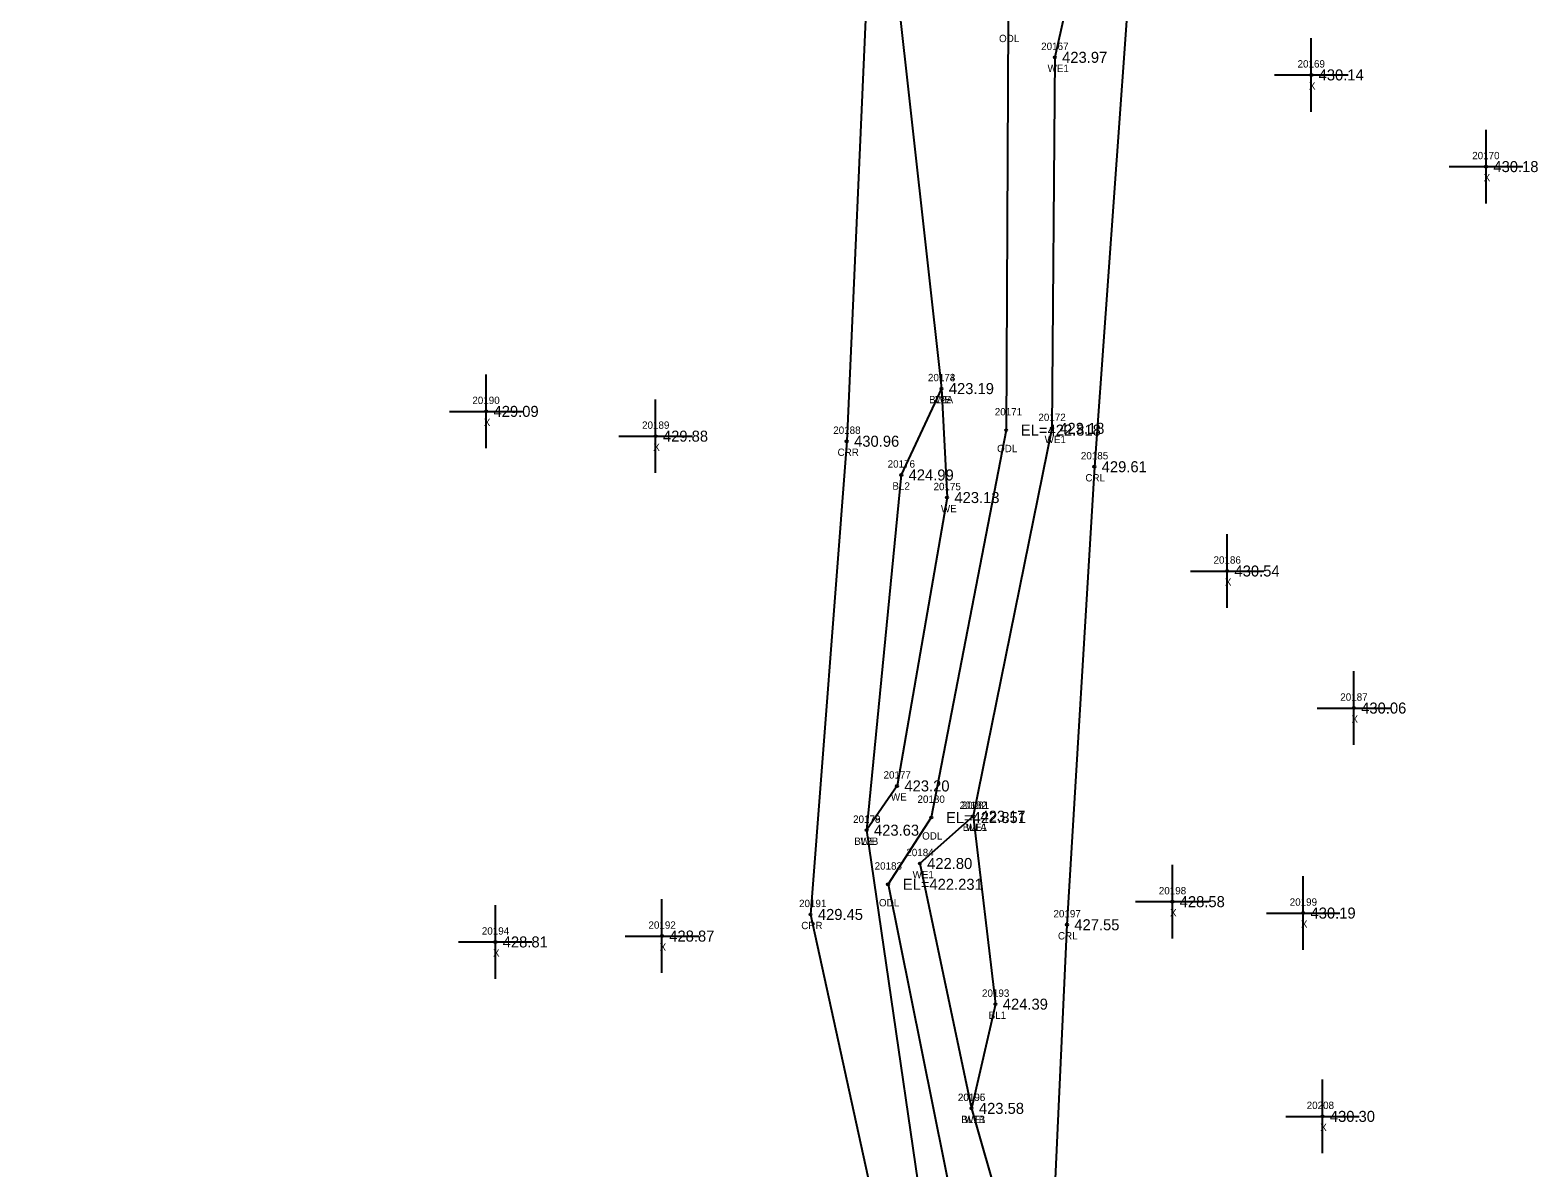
# Model space of a CAD drawing. Extents: x 1858461 to 1858936, y 1147060 to 1148183.
# Drawn here: x 1858722.2 to 1858927.2, y 1147876.4 to 1148031.1 of the extents above; entities that cross this region are included whole.
import ezdxf

# ---------------------------------------------------------------- set-up
doc = ezdxf.new("R2010")
doc.units = 0
for name, color, linetype in [('RD_DTM_BkLn1', 7, 'Continuous'), ('RD_DTM_BkLn_txCode', 7, 'Continuous'), ('RD_EX_H2O', 7, 'Continuous'), ('RD_EX_H2O_txCode', 7, 'Continuous'), ('RD_EX_Misc', 7, 'Continuous'), ('RD_EX_Misc_txCode', 7, 'Continuous'), ('RD_EX_TX_H2O_ELEV', 7, 'Continuous'), ('RD_EX_TX_Misc_ELEV', 7, 'Continuous'), ('RD_SMD_Locator', 7, 'Continuous')]:
    doc.layers.add(name, color=color, linetype=linetype)

msp = doc.modelspace()

# ---------------------------------------------------------------- linework, layer by layer
at = {"layer": 'RD_DTM_BkLn1'}
for points in [[(1858846.14, 1147982.36), (1858840.67, 1147970.61), (1858835.96, 1147922.3)], [(1858850.44, 1147924.2), (1858853.48, 1147898.64), (1858850.23, 1147884.47)]]:
    msp.add_lwpolyline(points, dxfattribs=at)
at = {"layer": 'RD_EX_H2O'}
for points in [[(1858883.69, 1148147.48), (1858852.78, 1148112.64), (1858836.04, 1148037.73), (1858833.26, 1147975.2), (1858828.33, 1147910.84), (1858842, 1147848.22), (1858847.52, 1147794.04), (1858841.16, 1147786.48), (1858816.23, 1147769.28), (1858759.58, 1147742.8), (1858751.47, 1147732.35), (1858731.2, 1147689.66), (1858724.77, 1147677.64), (1858718.76, 1147662.14), (1858713.87, 1147646.5), (1858696.23, 1147629.99), (1858681.73, 1147631.9), (1858663.61, 1147613.98)], [(1858909.91, 1148115.72), (1858902.77, 1148116.75), (1858903.07, 1148125.04), (1858896.61, 1148132.76), (1858873.78, 1148129.33), (1858855.27, 1148111.83), (1858840.09, 1148036.93), (1858846.14, 1147982.36), (1858846.9, 1147967.54), (1858840.1, 1147928.32), (1858835.96, 1147922.3), (1858846.22, 1147851.69), (1858849.56, 1147834.44), (1858863.29, 1147789.22), (1858867.71, 1147772.35), (1858865.71, 1147761.59), (1858842.61, 1147761.06), (1858828.27, 1147754.21), (1858821.34, 1147763.04), (1858764.94, 1147737.1), (1858734.3, 1147688.97), (1858719.03, 1147640.86), (1858697.04, 1147613.49)], [(1858867.04, 1148108.26), (1858855.22, 1148032.48), (1858854.94, 1147976.71), (1858844.75, 1147924.02), (1858838.88, 1147914.94), (1858851.14, 1147854.11), (1858872.36, 1147792.48), (1858884.3, 1147779.68), (1858885.3, 1147773.97), (1858872.32, 1147746.91), (1858824.97, 1147749.39), (1858805.62, 1147746.07), (1858768.36, 1147727.81), (1858744.99, 1147687.5), (1858739.82, 1147673.18), (1858724.58, 1147638.24), (1858698.73, 1147607.87)], [(1858878.92, 1148104.66), (1858861.55, 1148027.41), (1858861.16, 1147976.95), (1858850.44, 1147924.2), (1858843.19, 1147917.77), (1858850.23, 1147884.47), (1858857.83, 1147857.85), (1858871.27, 1147824.7), (1858889.75, 1147780), (1858881.97, 1147738.22), (1858867.37, 1147736.75), (1858826.32, 1147742.88), (1858795.91, 1147734.53), (1858775.64, 1147718.51), (1858753.77, 1147690.47), (1858731.96, 1147634.67), (1858700.72, 1147599.99)], [(1858879.83, 1148102.54), (1858871.42, 1148034.27), (1858866.93, 1147971.73), (1858863.21, 1147909.44), (1858860.9, 1147860.04), (1858873.82, 1147825.54), (1858891.79, 1147781.55), (1858894.95, 1147773.07), (1858887.01, 1147735.25), (1858825.08, 1147733.03), (1858791.14, 1147702.41), (1858765.02, 1147654.77), (1858740.99, 1147628.76), (1858706.35, 1147596.83), (1858671.87, 1147580.02), (1858637.61, 1147560.56), (1858613.46, 1147539.88), (1858609.2, 1147499), (1858608.26, 1147474.71), (1858583.43, 1147442.99), (1858542.68, 1147417.32), (1858497.34, 1147430.55)]]:
    msp.add_lwpolyline(points, dxfattribs=at)
at = {"layer": 'RD_EX_Misc'}
for p, q in [((1858896.43, 1148020.02), (1858896.43, 1148030.02)), ((1858891.43, 1148025.02), (1858901.43, 1148025.02)), ((1858920.2, 1148007.55), (1858920.2, 1148017.55)), ((1858915.2, 1148012.55), (1858925.2, 1148012.55)), ((1858784.22, 1147974.26), (1858784.22, 1147984.26)), ((1858779.22, 1147979.26), (1858789.22, 1147979.26)), ((1858807.26, 1147970.89), (1858807.26, 1147980.89)), ((1858802.26, 1147975.89), (1858812.26, 1147975.89)), ((1858884.99, 1147952.55), (1858884.99, 1147962.55)), ((1858879.99, 1147957.55), (1858889.99, 1147957.55)), ((1858902.22, 1147933.91), (1858902.22, 1147943.91)), ((1858897.22, 1147938.91), (1858907.22, 1147938.91)), ((1858877.54, 1147907.58), (1858877.54, 1147917.58)), ((1858895.33, 1147906.03), (1858895.33, 1147916.03)), ((1858785.47, 1147902.1), (1858785.47, 1147912.1)), ((1858808.12, 1147902.9), (1858808.12, 1147912.9)), ((1858872.54, 1147912.58), (1858882.54, 1147912.58)), ((1858890.33, 1147911.03), (1858900.33, 1147911.03)), ((1858803.12, 1147907.9), (1858813.12, 1147907.9)), ((1858780.47, 1147907.1), (1858790.47, 1147907.1)), ((1858897.96, 1147878.38), (1858897.96, 1147888.38)), ((1858892.96, 1147883.38), (1858902.96, 1147883.38))]:
    msp.add_line(p, q, dxfattribs=at)
at = {"layer": 'RD_SMD_Locator'}
for centre in [(1858861.55, 1148027.41), (1858896.43, 1148025.02), (1858920.2, 1148012.55), (1858846.14, 1147982.36), (1858846.14, 1147982.36), (1858784.22, 1147979.26), (1858861.16, 1147976.95), (1858807.26, 1147975.89), (1858833.26, 1147975.2), (1858854.94, 1147976.71), (1858866.93, 1147971.73), (1858840.67, 1147970.61), (1858846.9, 1147967.54), (1858884.99, 1147957.55), (1858902.22, 1147938.91), (1858840.1, 1147928.32), (1858844.75, 1147924.02), (1858850.44, 1147924.2), (1858850.44, 1147924.2), (1858835.96, 1147922.3), (1858835.96, 1147922.3), (1858843.19, 1147917.77), (1858838.88, 1147914.94), (1858877.54, 1147912.58), (1858828.33, 1147910.84), (1858863.21, 1147909.44), (1858895.33, 1147911.03), (1858808.12, 1147907.9), (1858785.47, 1147907.1), (1858853.48, 1147898.64), (1858850.23, 1147884.47), (1858850.23, 1147884.47), (1858897.96, 1147883.38)]:
    msp.add_circle(centre, 0.15, dxfattribs=at)

# ---------------------------------------------------------------- texts
at = {"layer": 'RD_DTM_BkLn_txCode'}
for s, p in [('20174', (1858844.3, 1147983.36)), ('BL2A', (1858844.45, 1147980.36)), ('20176', (1858838.82, 1147971.61)), ('BL2', (1858839.47, 1147968.61)), ('20182', (1858848.61, 1147925.2)), ('20179', (1858834.12, 1147923.3)), ('BL1A', (1858849.03, 1147922.2)), ('BL2B', (1858834.28, 1147920.3)), ('20193', (1858851.65, 1147899.64)), ('BL1', (1858852.56, 1147896.64)), ('20195', (1858848.39, 1147885.47)), ('BL1B', (1858848.83, 1147882.47))]:
    msp.add_text(s, height=1, dxfattribs=at).set_placement(p)
at = {"layer": 'RD_EX_H2O_txCode'}
for s, p in [('ODL', (1858853.97, 1148029.48)), ('20167', (1858859.7, 1148028.41)), ('WE1', (1858860.57, 1148025.41)), ('20173', (1858844.3, 1147983.36)), ('WE', (1858845.3, 1147980.36)), ('20171', (1858853.39, 1147978.71)), ('20188', (1858831.42, 1147976.2)), ('20172', (1858859.32, 1147977.95)), ('WE1', (1858860.17, 1147974.95)), ('CRR', (1858832.01, 1147973.2)), ('ODL', (1858853.7, 1147973.71)), ('20185', (1858865.1, 1147972.73)), ('20175', (1858845.06, 1147968.54)), ('CRL', (1858865.71, 1147969.73)), ('WE', (1858846.06, 1147965.54)), ('20177', (1858838.26, 1147929.32)), ('WE', (1858839.26, 1147926.32)), ('20180', (1858842.88, 1147926.02)), ('20181', (1858848.89, 1147925.2)), ('20178', (1858834.12, 1147923.3)), ('ODL', (1858843.51, 1147921.02)), ('WE1', (1858849.46, 1147922.2)), ('WE', (1858835.12, 1147920.3)), ('20184', (1858841.36, 1147918.77)), ('20183', (1858837.05, 1147916.94)), ('WE1', (1858842.21, 1147915.77)), ('20191', (1858826.77, 1147911.84)), ('ODL', (1858837.64, 1147911.94)), ('20197', (1858861.37, 1147910.44)), ('CRR', (1858827.07, 1147908.84)), ('CRL', (1858861.98, 1147907.44)), ('20196', (1858848.37, 1147885.47)), ('WE1', (1858849.24, 1147882.47))]:
    msp.add_text(s, height=1, dxfattribs=at).set_placement(p)
at = {"layer": 'RD_EX_Misc_txCode'}
for s, p in [('20169', (1858894.57, 1148026.02)), ('X', (1858896.11, 1148023.02)), ('20170', (1858918.32, 1148013.55)), ('X', (1858919.88, 1148010.55)), ('20190', (1858782.34, 1147980.26)), ('X', (1858783.9, 1147977.26)), ('20189', (1858805.42, 1147976.89)), ('X', (1858806.94, 1147973.89)), ('20186', (1858883.14, 1147958.55)), ('X', (1858884.68, 1147955.55)), ('20187', (1858900.38, 1147939.91)), ('X', (1858901.9, 1147936.91)), ('20198', (1858875.7, 1147913.58)), ('X', (1858877.22, 1147910.58)), ('20199', (1858893.5, 1147912.03)), ('20192', (1858806.29, 1147908.9)), ('X', (1858895.02, 1147909.03)), ('20194', (1858783.63, 1147908.1)), ('X', (1858785.15, 1147905.1)), ('X', (1858807.81, 1147905.9)), ('20208', (1858895.81, 1147884.38)), ('X', (1858897.65, 1147881.38))]:
    msp.add_text(s, height=1, dxfattribs=at).set_placement(p)
at = {"layer": 'RD_EX_TX_H2O_ELEV'}
for s, p in [('423.97', (1858862.55, 1148026.66)), ('423.19', (1858847.14, 1147981.61)), ('EL=422.818', (1858856.94, 1147975.96)), ('423.18', (1858862.16, 1147976.2)), ('430.96', (1858834.26, 1147974.45)), ('429.61', (1858867.93, 1147970.98)), ('423.13', (1858847.9, 1147966.79)), ('423.20', (1858841.1, 1147927.57)), ('EL=422.851', (1858846.75, 1147923.27)), ('423.17', (1858851.44, 1147923.45)), ('423.63', (1858836.96, 1147921.55)), ('422.80', (1858844.19, 1147917.02)), ('EL=422.231', (1858840.88, 1147914.19)), ('429.45', (1858829.33, 1147910.09)), ('427.55', (1858864.21, 1147908.69)), ('423.58', (1858851.23, 1147883.72))]:
    msp.add_text(s, height=1.5, dxfattribs=at).set_placement(p)
at = {"layer": 'RD_EX_TX_Misc_ELEV'}
for s, p in [('430.14', (1858897.43, 1148024.27)), ('430.18', (1858921.2, 1148011.8)), ('423.19', (1858847.14, 1147981.61)), ('429.09', (1858785.22, 1147978.51)), ('429.88', (1858808.26, 1147975.14)), ('424.99', (1858841.67, 1147969.86)), ('430.54', (1858885.99, 1147956.8)), ('430.06', (1858903.22, 1147938.16)), ('423.17', (1858851.44, 1147923.45)), ('423.63', (1858836.96, 1147921.55)), ('428.58', (1858878.54, 1147911.83)), ('430.19', (1858896.33, 1147910.28)), ('428.81', (1858786.47, 1147906.35)), ('428.87', (1858809.12, 1147907.15)), ('424.39', (1858854.48, 1147897.89)), ('423.58', (1858851.23, 1147883.72)), ('430.30', (1858898.96, 1147882.63))]:
    msp.add_text(s, height=1.5, dxfattribs=at).set_placement(p)

doc.saveas('drawing.dxf')
